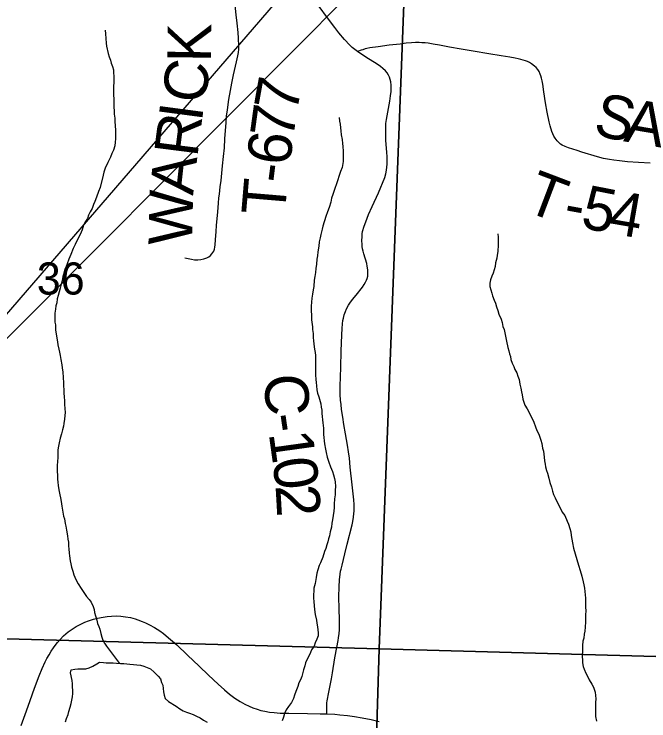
# Model space of a CAD drawing. Extents: x -7.9 to 76.1, y 0 to 22.
# Drawn here: x 5.777 to 6.604, y 17.154 to 18.075 of the extents above; entities that cross this region are included whole.
import ezdxf

# ---------------------------------------------------------------- set-up
doc = ezdxf.new("R2010")
doc.units = 0
for name, color, linetype in [('GM_X_County_Road', 7, 'Continuous'), ('GM_X_County_Road_Text', 7, 'Continuous'), ('GM_X_Minor_River', 7, 'Continuous'), ('GM_X_Section', 7, 'Continuous'), ('GM_X_Section_Text', 7, 'Continuous'), ('GM_X_State_Route', 7, 'Continuous'), ('GM_X_Township_Road', 7, 'Continuous'), ('GM_X_Township_Road_Text', 7, 'Continuous'), ('SH_Text', 7, 'Continuous')]:
    doc.layers.add(name, color=color, linetype=linetype)

msp = doc.modelspace()

# ---------------------------------------------------------------- linework, layer by layer
at = {"layer": 'GM_X_County_Road'}
msp.add_lwpolyline([(6.18494, 17.16283), (6.18479, 17.17377), (6.18495, 17.17731), (6.1852, 17.17985), (6.18725, 17.19144), (6.19104, 17.20854), (6.19235, 17.21635), (6.19539, 17.236), (6.19786, 17.24964), (6.19959, 17.25877), (6.20016, 17.26222), (6.20074, 17.26765), (6.20115, 17.27258), (6.20131, 17.27619), (6.20124, 17.28531), (6.20091, 17.29982), (6.20026, 17.31569), (6.20066, 17.32872), (6.20131, 17.33784), (6.20214, 17.34483), (6.20279, 17.34894), (6.20329, 17.35133), (6.2046, 17.35675), (6.20827, 17.37145), (6.21147, 17.38429), (6.21781, 17.40946), (6.21871, 17.41388), (6.21958, 17.4194), (6.22012, 17.42415), (6.22032, 17.42696), (6.22047, 17.43049), (6.2203, 17.43583), (6.21981, 17.44208), (6.21763, 17.46157), (6.21537, 17.48441), (6.21422, 17.49627), (6.21315, 17.5043), (6.21184, 17.51302), (6.20929, 17.52806), (6.20715, 17.5399), (6.2055, 17.54976), (6.20411, 17.55963), (6.20329, 17.56612), (6.20279, 17.57163), (6.2023, 17.57919), (6.20222, 17.59062), (6.20263, 17.60188), (6.20312, 17.61462), (6.20361, 17.6355), (6.20419, 17.65712), (6.2046, 17.66542), (6.20509, 17.67118), (6.20567, 17.67561), (6.20632, 17.67865), (6.20756, 17.68302), (6.20896, 17.68737), (6.2106, 17.69107), (6.21289, 17.69549), (6.21561, 17.69976), (6.21852, 17.70357), (6.22457, 17.71088), (6.22949, 17.71685), (6.23132, 17.71929), (6.23345, 17.72239), (6.23526, 17.72543), (6.23641, 17.72823), (6.23723, 17.73053), (6.23806, 17.73365), (6.2383, 17.7362), (6.23839, 17.7385), (6.2383, 17.74129), (6.23798, 17.74417), (6.23756, 17.74647), (6.23674, 17.74992), (6.23312, 17.76234), (6.23214, 17.76596), (6.23148, 17.76899), (6.23099, 17.77195), (6.23074, 17.77516), (6.23058, 17.77943), (6.23074, 17.78503), (6.23099, 17.78848), (6.23148, 17.7916), (6.23328, 17.79842), (6.23542, 17.80418), (6.23929, 17.81363), (6.24381, 17.82415), (6.25219, 17.84224), (6.26041, 17.86221), (6.26173, 17.86682), (6.26255, 17.87158), (6.26304, 17.87561), (6.26321, 17.87947), (6.26329, 17.88392), (6.26321, 17.88901), (6.2628, 17.89501), (6.26181, 17.91038), (6.26156, 17.91836), (6.26148, 17.92378), (6.26156, 17.92871), (6.26181, 17.93225), (6.26255, 17.93784), (6.26699, 17.96143), (6.26798, 17.96842), (6.26847, 17.97393), (6.26863, 17.97886), (6.26847, 17.98239), (6.26806, 17.98683), (6.2674, 17.98995), (6.2665, 17.99259), (6.2651, 17.99547), (6.26329, 17.99825), (6.26107, 18.00097), (6.25762, 18.00426), (6.25458, 18.00681), (6.24924, 18.01042), (6.23674, 18.01815), (6.22482, 18.02629), (6.22129, 18.02892), (6.21792, 18.03163), (6.21495, 18.03451), (6.20772, 18.04191), (6.20033, 18.0507), (6.19523, 18.05736), (6.18569, 18.07018), (6.1746, 18.08498)], dxfattribs=at)
at = {"layer": 'GM_X_Minor_River'}
for points in [[(5.89592, 18.05403), (5.89637, 18.0491), (5.89682, 18.04341), (5.89729, 18.03696), (5.89772, 18.03317), (5.89975, 18.0237), (5.90133, 18.01916), (5.9029, 18.01501), (5.90371, 18.01122), (5.90567, 18.00669), (5.90687, 18.00215), (5.90704, 17.98999), (5.90709, 17.9862), (5.90679, 17.9805), (5.90716, 17.95316), (5.90759, 17.94936), (5.90766, 17.94442), (5.90849, 17.9395), (5.90855, 17.93494), (5.90946, 17.92394), (5.90962, 17.91254), (5.90892, 17.90798), (5.9086, 17.90341), (5.90679, 17.89769), (5.90457, 17.89348), (5.90274, 17.88852), (5.89942, 17.88164), (5.89612, 17.87399), (5.89429, 17.86903), (5.8932, 17.86522), (5.88925, 17.84921), (5.88743, 17.84387), (5.88487, 17.83661), (5.88268, 17.83088), (5.88084, 17.82668), (5.87901, 17.82172), (5.87642, 17.81712), (5.87421, 17.81291), (5.87275, 17.80871), (5.87053, 17.80451), (5.86794, 17.79991), (5.86613, 17.79381), (5.86318, 17.78769), (5.85949, 17.78042), (5.85691, 17.77469), (5.85433, 17.76933), (5.85102, 17.76169), (5.84883, 17.75558), (5.84626, 17.74947), (5.84481, 17.74489), (5.84263, 17.73802), (5.8408, 17.73305), (5.83974, 17.72734), (5.83866, 17.72315), (5.83722, 17.71781), (5.83615, 17.71323), (5.8347, 17.70828), (5.83362, 17.7037), (5.83293, 17.69875), (5.83185, 17.69456), (5.83115, 17.69037), (5.83047, 17.68504), (5.83052, 17.68124), (5.8302, 17.67744), (5.83025, 17.67364), (5.83106, 17.66985), (5.83115, 17.66301), (5.83198, 17.65808), (5.83281, 17.65278), (5.83364, 17.64785), (5.83407, 17.64405), (5.83566, 17.63838), (5.83648, 17.63459), (5.8373, 17.63004), (5.83813, 17.62473), (5.83936, 17.61791), (5.83979, 17.61412), (5.84063, 17.60843), (5.84158, 17.59438), (5.84163, 17.59058), (5.84209, 17.58527), (5.84215, 17.58071), (5.84259, 17.57654), (5.84305, 17.57046), (5.8431, 17.56666), (5.84357, 17.56059), (5.84363, 17.55603), (5.843, 17.5469), (5.84231, 17.54157), (5.84161, 17.53776), (5.84016, 17.53318), (5.83909, 17.52785), (5.83728, 17.52212), (5.83584, 17.51602), (5.83514, 17.51183), (5.83445, 17.50726), (5.83415, 17.50118), (5.83421, 17.497), (5.83359, 17.48673), (5.83327, 17.48293), (5.83332, 17.47913)], [(6.20083, 17.94045), (6.20128, 17.93551), (6.20209, 17.93173), (6.20254, 17.9268), (6.20297, 17.923), (6.20342, 17.91769), (6.20464, 17.91163), (6.20509, 17.90632), (6.20552, 17.90253), (6.20598, 17.89645), (6.20617, 17.88278), (6.20476, 17.87517), (6.20256, 17.86982), (6.19711, 17.85265), (6.19564, 17.84883), (6.19382, 17.84387), (6.19274, 17.83967), (6.1909, 17.83509), (6.18984, 17.82976), (6.18804, 17.8229), (6.18584, 17.81717), (6.18365, 17.81106), (6.17965, 17.79847), (6.17857, 17.79466), (6.17715, 17.7878), (6.17607, 17.7836), (6.175, 17.77827), (6.17432, 17.77256), (6.17328, 17.76533), (6.1726, 17.76), (6.17191, 17.75544), (6.17124, 17.74897), (6.17055, 17.74326), (6.17024, 17.73831), (6.16918, 17.73298), (6.16849, 17.72803), (6.16784, 17.72005), (6.16715, 17.71548), (6.16609, 17.70976), (6.1654, 17.70482), (6.16471, 17.69949), (6.16441, 17.69416), (6.16449, 17.68809), (6.16495, 17.68239), (6.16503, 17.6767), (6.16591, 17.66759), (6.16597, 17.66379), (6.16679, 17.65886), (6.16687, 17.65316), (6.1673, 17.64937), (6.16774, 17.64482), (6.16859, 17.63837), (6.16941, 17.63382), (6.16984, 17.63003), (6.17019, 17.60496), (6.17066, 17.59888), (6.17071, 17.5947), (6.17115, 17.59053), (6.17198, 17.58522), (6.1728, 17.58105), (6.17438, 17.57613), (6.17679, 17.56705), (6.1776, 17.56288), (6.17842, 17.55871), (6.17848, 17.55453), (6.17891, 17.55074), (6.17935, 17.54618), (6.1794, 17.54239), (6.18026, 17.53518), (6.18037, 17.5272), (6.18167, 17.51506), (6.18291, 17.50785), (6.18373, 17.50369), (6.18533, 17.49763), (6.18732, 17.4912), (6.18968, 17.48477), (6.19204, 17.47872), (6.19361, 17.47456), (6.19482, 17.46964), (6.19563, 17.46547), (6.1961, 17.4594), (6.19579, 17.45445), (6.19549, 17.44837), (6.19481, 17.44304), (6.19452, 17.43619), (6.1942, 17.43201), (6.19389, 17.42707), (6.19216, 17.41564), (6.19146, 17.41145), (6.19077, 17.40612), (6.18933, 17.4004), (6.18827, 17.39507), (6.18718, 17.39126), (6.18611, 17.38706), (6.18464, 17.38324), (6.18357, 17.37866), (6.18173, 17.37446), (6.17956, 17.36721), (6.17662, 17.35995), (6.17478, 17.35612), (6.17296, 17.35078)], [(6.40768, 17.78866), (6.40812, 17.78411), (6.40826, 17.77424), (6.40762, 17.76549), (6.40693, 17.76092), (6.40623, 17.75673), (6.40479, 17.75101), (6.4041, 17.74607), (6.40264, 17.74187), (6.40157, 17.7373), (6.39972, 17.73347), (6.39827, 17.72851), (6.39719, 17.72432), (6.39725, 17.72014), (6.39845, 17.7156), (6.39965, 17.71144), (6.40046, 17.70765), (6.40281, 17.70236), (6.40438, 17.6982), (6.40597, 17.69328), (6.40755, 17.68875), (6.40913, 17.68383), (6.41187, 17.67741), (6.41307, 17.67325), (6.41428, 17.66794), (6.41585, 17.66379), (6.4179, 17.65318), (6.41909, 17.64863), (6.42073, 17.6403), (6.42192, 17.63613), (6.42273, 17.63234), (6.42392, 17.62856), (6.42473, 17.62477), (6.42631, 17.62024), (6.42865, 17.61571), (6.42984, 17.61193), (6.43256, 17.6074), (6.43375, 17.60324), (6.43533, 17.5987), (6.43617, 17.59263), (6.43739, 17.58733), (6.43859, 17.58279), (6.4394, 17.57862), (6.44023, 17.57331), (6.44143, 17.56915), (6.443, 17.56537), (6.44572, 17.56047), (6.4539, 17.54462), (6.45706, 17.53555), (6.45902, 17.53139), (6.46096, 17.52762), (6.46216, 17.52346), (6.46373, 17.51968), (6.46493, 17.51514), (6.46577, 17.50907), (6.46696, 17.50529), (6.46783, 17.49732), (6.46865, 17.49277), (6.46947, 17.4886), (6.4699, 17.48481), (6.4711, 17.48026), (6.47229, 17.47648), (6.4739, 17.47004), (6.47549, 17.46437), (6.47747, 17.45831), (6.47868, 17.45339), (6.48026, 17.44885), (6.48221, 17.44432), (6.48416, 17.44055), (6.48689, 17.43564), (6.49157, 17.42583), (6.49505, 17.42132), (6.4978, 17.41413), (6.49975, 17.41036), (6.50134, 17.40468), (6.50255, 17.40014), (6.50337, 17.39521), (6.50419, 17.39066), (6.50502, 17.38573), (6.50625, 17.37891), (6.50825, 17.37172), (6.51263, 17.35658), (6.515, 17.34977), (6.51699, 17.34258), (6.51862, 17.335), (6.5198, 17.33122), (6.52063, 17.32667), (6.52194, 17.31377), (6.52204, 17.30693), (6.52172, 17.30237), (6.52218, 17.29668), (6.52186, 17.29249), (6.52192, 17.28831), (6.52199, 17.28299), (6.52133, 17.27576), (6.52102, 17.27082), (6.52032, 17.26663), (6.51963, 17.26168), (6.51855, 17.25787), (6.51787, 17.25216), (6.51794, 17.24684)], [(5.83332, 17.47913), (5.83378, 17.47344), (5.83384, 17.46887), (5.83427, 17.46508), (5.83472, 17.46053), (5.83555, 17.45484), (5.83678, 17.4484), (5.83759, 17.44461), (5.8388, 17.43968), (5.83964, 17.43362), (5.84047, 17.4283), (5.84172, 17.42072), (5.84291, 17.41694), (5.84374, 17.41125), (5.84455, 17.40746), (5.84538, 17.40253), (5.847, 17.39495), (5.84744, 17.39078), (5.84826, 17.38661), (5.84833, 17.38167), (5.84876, 17.37788), (5.84921, 17.37256), (5.84964, 17.36877), (5.85049, 17.36232), (5.8513, 17.35853), (5.85212, 17.35436), (5.85371, 17.34906), (5.85529, 17.34414), (5.85765, 17.3381), (5.86077, 17.33244), (5.86464, 17.32641), (5.8689, 17.32001), (5.87161, 17.31587), (5.87508, 17.31211), (5.87778, 17.30835), (5.88014, 17.30268), (5.88171, 17.2989), (5.88214, 17.29511), (5.88334, 17.29056), (5.88493, 17.28527), (5.88613, 17.28072), (5.8877, 17.27694), (5.88889, 17.27316), (5.89048, 17.26748), (5.89169, 17.26294), (5.89287, 17.25916), (5.89521, 17.25501), (5.89754, 17.25124), (5.91459, 17.22877)], [(6.17296, 17.35078), (6.17188, 17.34621), (6.17082, 17.34087), (6.16941, 17.33287), (6.16798, 17.32677), (6.16766, 17.32297), (6.16734, 17.3184), (6.16741, 17.31384), (6.16784, 17.30929), (6.1683, 17.30359), (6.16875, 17.29904), (6.16959, 17.29259), (6.17122, 17.28501), (6.17165, 17.28122), (6.17248, 17.27629), (6.17329, 17.2725), (6.17372, 17.26871), (6.1734, 17.26452), (6.17194, 17.26032), (6.16973, 17.25535), (6.16827, 17.25115), (6.16493, 17.24655), (6.16346, 17.24273), (6.16162, 17.2389), (6.15866, 17.23316), (6.15682, 17.22933), (6.15612, 17.22553), (6.1543, 17.22018), (6.15213, 17.21179), (6.1503, 17.20721), (6.14846, 17.20338), (6.14701, 17.1988), (6.14444, 17.19231), (6.14262, 17.18734), (6.14116, 17.18276), (6.13858, 17.17779), (6.13486, 17.17241), (6.13189, 17.16819), (6.12968, 17.16322), (6.12823, 17.15864), (6.1264, 17.15368)], [(6.51794, 17.24684), (6.51731, 17.23733), (6.51775, 17.23354), (6.5178, 17.22936), (6.51901, 17.22482), (6.52019, 17.22103), (6.52216, 17.21612), (6.52488, 17.21122), (6.52645, 17.20744), (6.52994, 17.20179), (6.53227, 17.19764), (6.53426, 17.19121), (6.53508, 17.18704), (6.53514, 17.18248), (6.53482, 17.17792), (6.53507, 17.15968), (6.5363, 17.15324)], [(5.84866, 17.1662), (5.85048, 17.17155), (5.85155, 17.1765), (5.85263, 17.1807), (5.85333, 17.18527), (5.85365, 17.18945), (5.85348, 17.20199), (5.85303, 17.20655), (5.85062, 17.21639), (5.85171, 17.22021), (5.85624, 17.22141), (5.86041, 17.22185), (5.8661, 17.22155), (5.87065, 17.22161), (5.87518, 17.22281), (5.88008, 17.22516), (5.88496, 17.22826), (5.88873, 17.23022), (5.89366, 17.2299), (5.89746, 17.22958), (5.90239, 17.22926), (5.90618, 17.22932), (5.91074, 17.229), (5.91605, 17.22869), (5.92022, 17.22875), (5.9244, 17.22805), (5.9282, 17.22772), (5.93275, 17.2274), (5.93731, 17.2267), (5.94187, 17.22638), (5.94643, 17.22531), (5.95482, 17.22162), (5.95981, 17.21751), (5.96481, 17.21226), (5.9679, 17.2085), (5.96948, 17.20396), (5.97105, 17.20019), (5.97193, 17.19146), (5.97274, 17.18729), (5.97432, 17.18313), (5.97855, 17.17901), (5.98849, 17.17306), (5.99346, 17.16971), (5.99767, 17.16711), (6.00187, 17.16527), (6.00568, 17.1638), (6.01063, 17.16197), (6.01483, 17.16012), (6.01979, 17.15791), (6.024, 17.15493), (6.02897, 17.15196)], [(5.8443, 17.15246), (5.84576, 17.15704), (5.84759, 17.16201), (5.84866, 17.1662)]]:
    msp.add_lwpolyline(points, dxfattribs=at)
at = {"layer": 'GM_X_Section'}
for points in [[(5.42161, 18.23625), (6.28986, 18.21295), (6.25293, 17.24785), (5.39529, 17.27094), (5.3971, 17.39528), (5.42068, 18.22297)], [(7.30832, 18.18256), (7.27135, 17.21935), (6.25293, 17.24785), (6.28986, 18.21295)], [(5.39529, 17.27094), (6.25293, 17.24785), (6.22272, 16.24155), (5.36783, 16.25786), (5.37022, 16.37046)], [(6.25293, 17.24785), (7.27135, 17.21935), (7.23119, 16.21858), (6.22272, 16.24155)]]:
    msp.add_lwpolyline(points, close=True, dxfattribs=at)
at = {"layer": 'GM_X_State_Route'}
msp.add_lwpolyline([(5.78648, 17.14785), (5.79339, 17.16701), (5.79812, 17.18023), (5.80398, 17.19658), (5.80991, 17.21247), (5.81372, 17.22217), (5.81791, 17.23098), (5.82012, 17.23526), (5.8228, 17.24001), (5.82558, 17.24462), (5.82859, 17.24911), (5.83068, 17.25195), (5.83399, 17.25608), (5.83748, 17.26005), (5.8418, 17.26457), (5.84795, 17.26985), (5.85286, 17.27346), (5.85823, 17.27688), (5.86318, 17.27957), (5.86939, 17.28242), (5.87417, 17.28427), (5.88068, 17.28631), (5.88585, 17.28763), (5.89354, 17.28914), (5.89855, 17.28982), (5.90411, 17.29032), (5.91036, 17.29056), (5.91627, 17.29032), (5.92244, 17.28958), (5.92884, 17.2884), (5.93511, 17.28677), (5.9387, 17.28562), (5.94424, 17.28351), (5.94838, 17.28167), (5.95381, 17.27903), (5.96042, 17.27535), (5.96715, 17.27103), (5.97188, 17.26759), (5.97545, 17.26476), (5.98919, 17.25275), (6.00341, 17.23926), (6.01862, 17.22505), (6.03074, 17.21333), (6.04303, 17.20162), (6.05134, 17.19422), (6.058, 17.18863), (6.06498, 17.18353), (6.07205, 17.17885), (6.07781, 17.17556), (6.08356, 17.17285), (6.08841, 17.17088), (6.094, 17.1689), (6.09901, 17.1675), (6.10411, 17.16627), (6.11027, 17.16528), (6.11628, 17.16459), (6.12389, 17.16392), (6.13518, 17.16372), (6.15945, 17.16341), (6.17594, 17.16315), (6.18494, 17.16283), (6.19527, 17.16246), (6.20192, 17.16188), (6.21177, 17.16087), (6.22088, 17.15957), (6.23079, 17.15798), (6.24237, 17.15558), (6.25306, 17.15312)], dxfattribs=at)
at = {"layer": 'GM_X_Township_Road'}
for points in [[(5.99964, 17.75712), (6.00831, 17.75539), (6.0123, 17.75481), (6.01456, 17.75471), (6.01682, 17.75481), (6.02064, 17.75521), (6.02465, 17.75611), (6.02838, 17.75732), (6.03099, 17.75879), (6.03315, 17.76046), (6.03498, 17.76247), (6.03634, 17.76435), (6.03739, 17.76616), (6.03822, 17.76842), (6.03897, 17.77129), (6.03942, 17.7743), (6.0398, 17.78078), (6.04048, 17.79163), (6.04108, 17.79954), (6.04259, 17.81733), (6.04357, 17.82878), (6.04417, 17.83541), (6.04477, 17.84023), (6.04598, 17.84987), (6.04711, 17.85824), (6.04899, 17.87708), (6.05017, 17.88929), (6.05125, 17.90058), (6.05208, 17.91256), (6.05268, 17.92326), (6.05344, 17.93336), (6.05427, 17.94203), (6.05525, 17.95016), (6.05721, 17.96365), (6.05924, 17.97526), (6.06113, 17.9849), (6.06338, 17.99605), (6.0673, 18.01286), (6.06873, 18.02054), (6.06949, 18.02491), (6.06994, 18.02928), (6.07017, 18.03372), (6.06986, 18.04375), (6.06934, 18.05083), (6.06806, 18.06334), (6.06677, 18.07412), (6.06527, 18.08669)], [(6.60625, 17.88067), (6.59096, 17.88174), (6.57657, 17.88264), (6.56605, 17.88362), (6.5589, 17.88444), (6.55298, 17.88535), (6.54517, 17.887), (6.53728, 17.88914), (6.51706, 17.89505), (6.51098, 17.89711), (6.5053, 17.89884), (6.49972, 17.90064), (6.49536, 17.90245), (6.49158, 17.90426), (6.48946, 17.90561), (6.48705, 17.90771), (6.485, 17.91001), (6.48229, 17.91346), (6.48081, 17.91585), (6.47933, 17.91881), (6.47801, 17.92209), (6.47579, 17.92933), (6.4744, 17.93468), (6.4719, 17.947), (6.46979, 17.95941), (6.46773, 17.97357), (6.46626, 17.98367), (6.46544, 17.9881), (6.46461, 17.99156), (6.46371, 17.99468), (6.46289, 17.9969), (6.46141, 18.00003), (6.45976, 18.00282), (6.45754, 18.00545), (6.45541, 18.00734), (6.45163, 18.0103), (6.44891, 18.01178), (6.44645, 18.01301), (6.44382, 18.01408), (6.44069, 18.01507), (6.43773, 18.01589), (6.43395, 18.01688), (6.43017, 18.0177), (6.4231, 18.01893), (6.4121, 18.02074), (6.39587, 18.0234), (6.37548, 18.02674), (6.35997, 18.02929), (6.34478, 18.03207), (6.33169, 18.03447), (6.32315, 18.03603), (6.31665, 18.0371), (6.31279, 18.03751), (6.30876, 18.03776), (6.30492, 18.0379), (6.30054, 18.03784), (6.29525, 18.03761), (6.28805, 18.03694), (6.28015, 18.03603), (6.26601, 18.0343), (6.2518, 18.03241), (6.2408, 18.03083), (6.23709, 18.0301), (6.23469, 18.02955), (6.23164, 18.02865), (6.22945, 18.02794), (6.22482, 18.02629)]]:
    msp.add_lwpolyline(points, dxfattribs=at)
at = {"layer": 'SH_Text'}
msp.add_lwpolyline([(6.54813, 18.58841), (6.54813, 18.43694), (5.55909, 17.44244)], close=True, dxfattribs=at)

# ---------------------------------------------------------------- texts
at = {"layer": 'GM_X_County_Road_Text'}
for s, rotation, p in [('C', 271.63948, (6.10371, 17.60566)), ('-', 278.25056, (6.10567, 17.55188)), ('1', 277.90345, (6.109, 17.52888)), ('0', 276.93848, (6.11378, 17.49446)), ('2', 273.2751, (6.11792, 17.46067))]:
    msp.add_text(s, height=0.05682, rotation=rotation, dxfattribs=at).set_placement(p)
at = {"layer": 'GM_X_Section_Text'}
msp.add_text('36', height=0.041856, rotation=0.00001, dxfattribs=at).set_placement((5.8069, 17.70947))
at = {"layer": 'GM_X_Township_Road_Text'}
for s, rotation, p in [('K', 89.23983, (6.03364, 18.01189)), ('C', 80.22263, (6.02482, 17.95619)), ('7', 79.74541, (6.14542, 17.94478)), ('S', 347.90823, (6.53042, 17.91792)), ('I', 82.43733, (6.02184, 17.93363)), ('7', 82.18045, (6.14076, 17.91073)), ('A', 350.40638, (6.57056, 17.90938)), ('R', 82.73652, (6.01595, 17.88742)), ('6', 82.74201, (6.13636, 17.87616)), ('A', 83.6594, (6.01046, 17.83797)), ('-', 82.82366, (6.13345, 17.85303)), ('T', 339.20218, (6.44069, 17.81926)), ('T', 85.20325, (6.12996, 17.8113)), ('W', 88.76876, (6.00913, 17.77348)), ('5', 348.84009, (6.51404, 17.797)), ('4', 350.18038, (6.5498, 17.78996)), ('-', 349.65996, (6.49129, 17.80114))]:
    msp.add_text(s, height=0.05682, rotation=rotation, dxfattribs=at).set_placement(p)

doc.saveas('drawing.dxf')
